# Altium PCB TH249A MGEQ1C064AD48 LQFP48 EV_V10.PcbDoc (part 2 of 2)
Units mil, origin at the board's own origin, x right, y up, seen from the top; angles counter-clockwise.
Board outline 3818.9 x 2637.8 mil, 2 copper layers (Top Layer, Bottom Layer); 103 components, 120 nets, 468 pads, 229 vias.
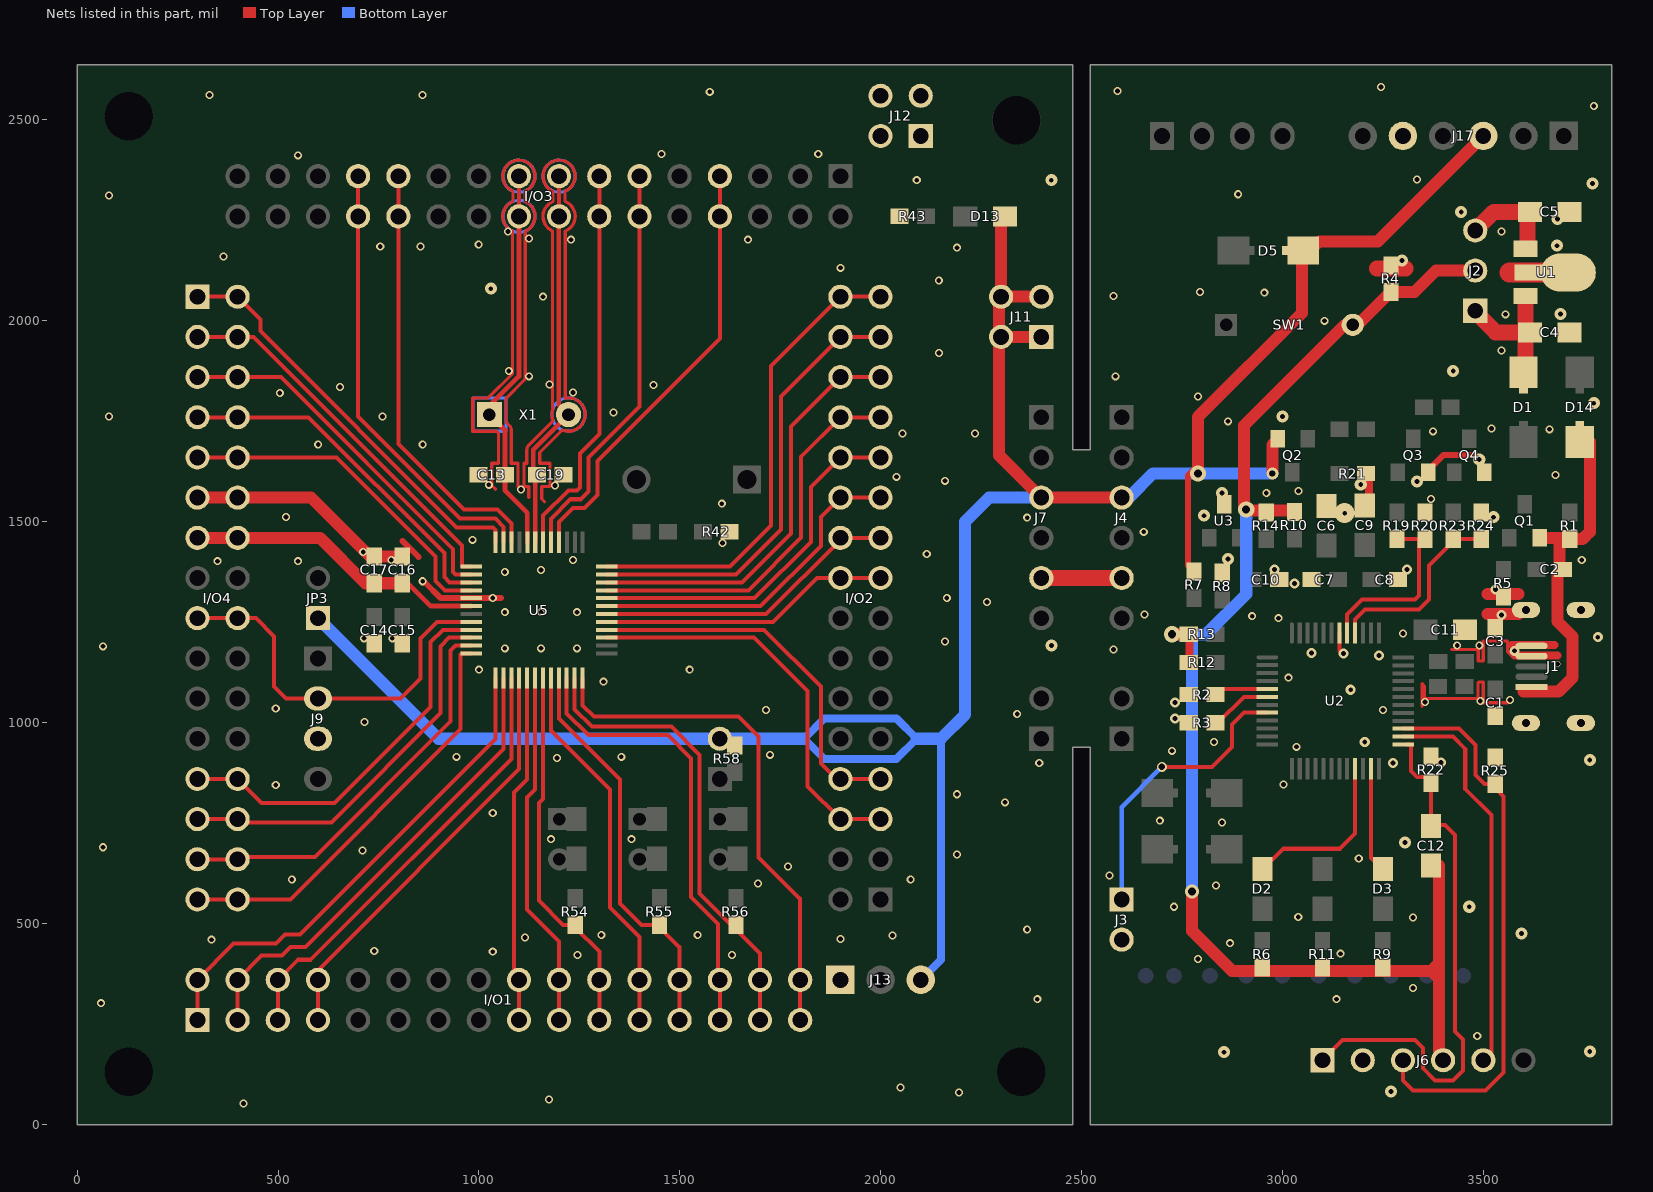
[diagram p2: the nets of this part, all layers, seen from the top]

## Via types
v1: diameter 20, hole 12, Top Layer to Bottom Layer, tented both sides, 163 vias
v2: diameter 30, hole 12, Top Layer to Bottom Layer, tented both sides, 26 vias
v3: diameter 25, hole 12, Top Layer to Bottom Layer, tented both sides, 16 vias
v4: diameter 25, hole 16, Top Layer to Bottom Layer, tented both sides, 13 vias
v5: diameter 40, hole 20, Top Layer to Bottom Layer, tented both sides, 5 vias
v6: diameter 30, hole 16, Top Layer to Bottom Layer, tented both sides, 3 vias
v7: diameter 35, hole 20, Top Layer to Bottom Layer, tented both sides, 1 vias
v8: diameter 50, hole 12, Top Layer to Bottom Layer, tented both sides, 1 vias
v9: diameter 15, hole 12, Top Layer to Bottom Layer, tented both sides, 1 vias

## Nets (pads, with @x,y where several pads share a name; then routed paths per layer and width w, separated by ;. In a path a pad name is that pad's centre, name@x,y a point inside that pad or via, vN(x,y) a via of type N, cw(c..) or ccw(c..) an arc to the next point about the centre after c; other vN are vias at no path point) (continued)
P01: I/O3.23 I/O3.24 U5.34 | length 1076.9
  Top Layer w10: I/O3.23@799.45,2360 I/O3.24@799.45,2260 799.45,1693.03 962.48,1530 1046.61,1530 1081.05,1495.56 U5.34@1081.05,1448.99
P02: I/O3.25 I/O3.26 U5.35 | length 1112.1
  Top Layer w10: I/O3.25@699.45,2360 I/O3.26@699.45,2260 699.45,1761.92 953.37,1508 1040.77,1508 1061.37,1487.41 U5.35@1061.37,1448.99
P03: I/O4.1 I/O4.2 U5.36 | length 1053.7
  Top Layer w10: I/O4.1@299.45,2060 I/O4.2@399.45,2060 ; I/O4.2@399.45,2036.48 I/O4.2@399.45,2060 ; U5.36@1041.68,1448.99 1041.68,1479.25 1034.93,1486 944.25,1486 455.93,1974.32 455.93,2003.52 I/O4.2@399.45,2060
P04: I/O4.3 I/O4.4 U5.37 | length 948.5
  Top Layer w10: I/O4.3@299.45,1960 I/O4.4@399.45,1960 438.59,1960 957.93,1440.66 957.93,1388.52 U5.37@980.71,1388.52
P05: I/O4.5 I/O4.6 U5.38 | length 932
  Top Layer w10: I/O4.5@299.45,1860 I/O4.6@399.45,1860 ; I/O4.6@409.45,1850 I/O4.6@399.45,1860 ; U5.38@980.71,1368.83 942.1,1368.83 935.93,1375 935.93,1431.55 507.48,1860 I/O4.6@399.45,1860
P06: I/O4.7 I/O4.8 U5.39 | length 886.8
  Top Layer w10: I/O4.7@299.45,1760 I/O4.8@399.45,1760 576.37,1760 913.93,1422.44 913.93,1362 926.78,1349.15 U5.39@980.71,1349.15
P07: I/O4.9 I/O4.10 U5.40 | length 853.8
  Top Layer w10: I/O4.9@299.45,1660 I/O4.10@399.45,1660 645.25,1660 891.93,1413.32 891.93,1352.52 914.99,1329.46 U5.40@980.71,1329.46
P10: I/O4.25 I/O4.26 U5.45 | length 979.5
  Top Layer w10: I/O4.25@299.45,860 I/O4.26@399.45,860 459.45,800 640.93,800 879.45,1038.52 879.45,1200.36 910.13,1231.04 U5.45@980.71,1231.04
P11: I/O4.27 I/O4.28 U5.46 | length 982.6
  Top Layer w10: I/O4.27@299.45,760 I/O4.28@399.45,760 ; I/O4.28@389.45,760 I/O4.28@399.45,760 ; U5.46@980.71,1211.35 925.8,1211.35 904.45,1190 904.45,1023.52 632.69,751.76 407.69,751.76 I/O4.28@399.45,760
P12: I/O4.29 I/O4.30 U5.47 | length 1004.7
  Top Layer w10: I/O4.29@299.45,660 I/O4.30@399.45,660 404.94,665.49 591.42,665.49 929.45,1003.52 929.45,1179.64 941.47,1191.67 U5.47@980.71,1191.67
P13: I/O4.31 I/O4.32 U5.48 | length 1043.3
  Top Layer w10: I/O4.31@299.45,560 I/O4.32@399.45,560 530.47,560 954.45,983.98 954.45,1169.29 957.14,1171.98 U5.48@980.71,1171.98
P14: I/O1.1 I/O1.2 U5.1 | length 1241.8
  Top Layer w10: I/O1.1@299.45,260 I/O1.2@299.45,360 389.45,450 494.45,450 517.44,472.99 555,472.99 1041.18,959.18 U5.1@1041.18,1111.01
P15: I/O1.3 I/O1.4 U5.2 | length 1176
  Top Layer w10: I/O1.3@399.45,260 I/O1.4@399.45,360 459.45,420 509.45,420 530.94,441.5 568.04,441.5 1060.87,934.32 U5.2@1060.87,1111.01
P16: I/O1.5 I/O1.6 U5.3 | length 1110.2
  Top Layer w10: I/O1.5@499.45,260 I/O1.6@499.45,360 549.45,410 581.09,410 1080.55,909.46 U5.3@1080.55,1111.01
P17: I/O1.7 I/O1.8 U5.4 | length 1058.4
  Top Layer w10: I/O1.7@599.45,260 I/O1.8@599.45,360 599.45,383.82 1100.24,884.6 U5.4@1100.24,1111.01
P20: I/O1.17 I/O1.18 U5.5 | length 869.3
  Top Layer w10: I/O1.17@1099.45,260 I/O1.18@1099.45,360 1087.63,371.82 1087.63,826.54 1119.92,858.83 U5.5@1119.92,1111.01
P21: I/O1.19 I/O1.20 U5.6 | length 892.5
  Top Layer w10: U5.6@1139.61,1111.01 1139.61,833.52 1119.45,813.36 1119.45,534.9 1199.45,454.9 I/O1.20@1199.45,360 I/O1.19@1199.45,260
P22: I/O1.21 I/O1.22 R54.1 U5.7 | length 924.8
  Top Layer w10: U5.7@1159.29,1111.01 1159.29,809.84 1149.45,800 1149.45,556.9 1209.35,497 R54.1@1239.45,497 1239.45,490 1299.45,430 I/O1.22@1299.45,370 ; I/O1.21@1299.45,260 I/O1.22@1299.45,360
P23: I/O1.23 I/O1.24 U5.8 | length 942.3
  Top Layer w10: U5.8@1178.98,1111.01 1178.98,980.47 1325.93,833.52 1325.93,540 1399.45,466.48 I/O1.24@1399.45,360 I/O1.23@1399.45,260
P24: I/O1.25 I/O1.26 R55.1 U5.9 | length 1002.3
  Top Layer w10: U5.9@1198.66,1111.01 1198.66,1010.79 1350.93,858.52 1350.93,550 1403.93,497 R55.1@1449.45,497 1449.45,490 1499.45,440 ; I/O1.25@1499.45,260 I/O1.26@1499.45,360 ; I/O1.26@1499.45,361.9 1499.45,440 ; 1499.45,441.9 1499.45,440
P25: I/O1.27 I/O1.28 U5.10 | length 1135.8
  Top Layer w10: U5.10@1218.35,1111.01 1218.35,1022.58 1272.14,968.79 1470.66,968.79 1528.24,911.21 1528.24,566.21 1595.19,499.26 1595.19,360 1595.19,355.74 I/O1.28@1599.45,351.48 ; I/O1.27@1599.45,260 I/O1.28@1599.45,351.48 ; I/O1.28@1599.45,360 I/O1.28@1599.45,351.48 ; I/O1.28@1600.93,350 I/O1.28@1599.45,351.48
P26: I/O1.29 I/O1.30 R56.1 U5.11 | length 1165.5
  Top Layer w10: U5.11@1238.03,1111.01 1238.03,1032.9 1280.93,990 1479.45,990 1549.45,920 1549.45,575 1627.45,497 R56.1@1639.45,497 1639.45,485 1699.45,425 I/O1.30@1699.45,360 I/O1.29@1699.45,260
P27: I/O1.31 I/O1.32 U5.12 | length 1286.3
  Top Layer w10: U5.12@1257.72,1111.01 1257.72,1043.22 1285.93,1015 1645.93,1015 1695.93,965 1695.93,665 1799.45,561.48 ; I/O1.31@1799.45,260 I/O1.32@1799.45,360 ; I/O1.32@1799.45,360.42 1799.45,561.48 ; 1799.45,561.9 1799.45,561.48
P32: I/O2.5 I/O2.6 U5.15 | length 1007
  Top Layer w10: U5.15@1318.19,1211.35 1685.04,1211.35 1817.94,1078.45 1817.94,841.51 I/O2.6@1899.45,760 I/O2.5@1999.45,760
P33: I/O2.7 I/O2.8 U5.16 | length 947.1
  Top Layer w10: U5.16@1318.19,1231.04 1709.89,1231.04 1850.93,1090 1850.93,898.52 1889.45,860 I/O2.8@1899.45,860 I/O2.7@1999.45,860
P34: I/O2.17 I/O2.18 U5.17 | length 726.5
  Top Layer w10: U5.17@1318.19,1250.72 1731.65,1250.72 1840.93,1360 I/O2.18@1899.45,1360 I/O2.17@1999.45,1360
P35: I/O2.19 I/O2.20 U5.18 | length 771.6
  Top Layer w10: U5.18@1318.19,1270.41 1714.86,1270.41 1896.95,1452.5 1899.45,1452.5 1906.95,1452.5 I/O2.20@1912.2,1457.76 ; I/O2.20@1899.45,1460 I/O2.19@1999.45,1460
P36: I/O2.21 I/O2.22 U5.19 | length 834.9
  Top Layer w10: U5.19@1318.19,1290.09 1701.02,1290.09 1850.68,1439.75 1850.68,1511.23 I/O2.22@1899.45,1560 I/O2.21@1999.45,1560
P37: I/O2.23 I/O2.24 U5.20 | length 906.3
  Top Layer w10: U5.20@1318.19,1309.78 1685.71,1309.78 1825.93,1450 1825.93,1586.48 I/O2.24@1899.45,1660 I/O2.23@1999.45,1660
P40: I/O2.25 I/O2.26 U5.21 | length 977.6
  Top Layer w10: U5.21@1318.19,1329.46 1670.39,1329.46 1801.18,1460.25 1801.18,1661.73 I/O2.26@1899.45,1760 I/O2.25@1999.45,1760
P41: I/O2.27 I/O2.28 U5.22 | length 1062.6
  Top Layer w10: U5.22@1318.19,1349.15 1655.08,1349.15 1776.43,1470.5 1776.43,1736.98 I/O2.28@1899.45,1860 ; I/O2.28@1885.82,1860 I/O2.28@1899.45,1860 ; I/O2.27@1999.45,1860 I/O2.28@1899.45,1860
P42: I/O2.29 I/O2.30 U5.23 | length 1120.3
  Top Layer w10: U5.23@1318.19,1368.83 1639.76,1368.83 1751.68,1480.75 1751.68,1812.24 I/O2.30@1899.45,1960 I/O2.29@1999.45,1960
P43: I/O2.31 I/O2.32 U5.24 | length 1191.7
  Top Layer w10: U5.24@1318.19,1388.52 1624.45,1388.52 1726.94,1491.01 1726.94,1887.49 I/O2.32@1899.45,2060 I/O2.31@1999.45,2060
P44: J6.5 U2.26 | length 977.3
  Top Layer w10: U2.26@3299.91,965.31 3424.14,965.31 3454.45,935 3454.45,835 3519.45,770 3519.45,180 J6.5@3499.45,160
P45: J6.3 R25.1 U2.27 | length 1381.3
  Top Layer w10: J6.3@3299.45,160 3299.45,110 3324.45,85 3504.45,85 3549.45,130 3549.45,816.22 R25.1@3524.41,841.26 ; U2.27@3299.91,984.99 3439.46,984.99 3479.45,945 3479.45,870 3502.45,847 R25.1@3529.45,847
P46: I/O3.7 I/O3.8 U5.28 | length 1093.5
  Top Layer w10: U5.28@1199.16,1448.99 1199.16,1498.91 1234.25,1534 1262.71,1534 1294.93,1566.23 1294.93,1651.23 1599.45,1955.74 I/O3.8@1599.45,2260 I/O3.7@1599.45,2360
P60: C13.1 I/O3.17 I/O3.18 U5.32 X1.1 | length 980.5
  Top Layer w10: I/O3.18@1099.45,2260 I/O3.17@1099.45,2360
  Top Layer w12: I/O3.18@1099.45,2260 1099.45,1861.64 1026.06,1788.25 X1.1@1026.06,1766.68 1064.49,1728.25 C13.1@1064.49,1616.68 1064.49,1577.9 1120.42,1521.97 U5.32@1120.42,1448.99
P61: C19.1 I/O3.15 I/O3.16 U5.31 X1.2 | length 945.4
  Top Layer w10: I/O3.16@1199.45,2260 I/O3.15@1199.45,2360
  Top Layer w12: C19.1@1135.2,1616.68 1135.2,1678.96 X1.2@1222.56,1766.32 ; U5.31@1140.11,1448.99 C19.1@1140.11,1602.44 ; I/O3.16@1198.74,2261.79 1198.74,2260 1198.74,1790.85 X1.2@1222.91,1766.68 X1.2@1222.56,1766.32 ; X1.2@1222.91,1765.97 X1.2@1222.56,1766.32
P62: I/O3.13 I/O3.14 U5.30 | length 981.4
  Top Layer w10: U5.30@1159.79,1448.99 1159.79,1515.22 1222.58,1578 1243.93,1578 1250.93,1585 1250.93,1669.45 1299.45,1717.97 I/O3.14@1299.45,2260 I/O3.13@1299.45,2360
P63: I/O3.11 I/O3.12 U5.29 | length 1016.9
  Top Layer w10: U5.29@1179.48,1448.99 1179.48,1507.06 1228.41,1556 1253.59,1556 1272.93,1575.34 1272.93,1660.34 1399.45,1786.86 I/O3.12@1399.45,2260 I/O3.11@1399.45,2360
PASS: D3.2 U2.23 | length 264.5
  Top Layer w10: U2.23@3219.75,885.65 3219.75,663.12 3248.43,634.45 D3.2@3249.45,633.43
RST: C12.2 J6.1 R22.2 U2.25 | length 1368.1
  Top Layer w10: J6.1@3099.45,160 3149.45,210 3329.45,210 3349.45,190 3349.45,140 3379.45,110 3424.45,110 3449.45,135 3449.45,211.22 3429.45,231.22 3429.45,719.96 3404.41,745 3384.45,745 3377.84,751.61 C12.2@3369.45,760 ; U2.25@3309.45,945.62 3318.83,945.62 3319.45,945 3319.45,880 3334.45,865 3369.45,865 R22.2@3369.45,850 C12.2@3369.45,760 ; C12.2@3369.45,750 C12.2@3369.45,760
RST_CTRL_51: R19.1 R20.1 U2.41 | length 455
  Top Layer w10: U2.41@3160.7,1223.13 3160.7,1269.12 3197.83,1306.26 3329.41,1306.26 3339.45,1316.3 R20.1@3339.45,1457 ; R19.1@3284.45,1457 R20.1@3339.45,1457 ; R20.1@3354.45,1457 R20.1@3339.45,1457
RST_CTRL_ARM: R23.1 R24.1 U2.40 | length 474.6
  Top Layer w10: U2.40@3180.38,1223.13 3180.38,1256.93 3204.71,1281.26 3339.41,1281.26 3364.45,1306.3 3364.45,1391.3 R23.1@3421.91,1448.76 ; R23.1@3424.45,1457 R24.1@3494.45,1457
TOOL_OPTION0: R2.1 U2.5 | length 135.2
  Top Layer w10: R2.1@2832.45,1070 2846.37,1083.92 U2.5@2961.93,1083.92
TOOL_OPTION1: R3.1 U2.6 | length 156.1
  Top Layer w10: R3.1@2832.45,1000 2839.45,1000 2903.68,1064.23 U2.6@2961.93,1064.23
USBOK: D2.2 U2.21 | length 430.2
  Top Layer w10: D2.2@2949.45,633.42 2950.47,634.45 3002.28,686.26 3142.87,686.26 3180.38,723.77 U2.21@3180.38,885.65
VCAP: C16.1 C17.1 I/O4.13 I/O4.14 U5.42 | length 762.6
  Top Layer w12: C16.1@809.45,1347 C16.1@820.45,1347 ; C16.1@820.09,1337.36 832.73,1337.36 ; C16.1@823.09,1347 832.73,1337.36 ; U5.42@980.71,1290.09 880,1290.09 832.73,1337.36
  Top Layer w20: C16.1@808.45,1336 C16.1@809.45,1336
  Top Layer w30: I/O4.13@299.45,1460 I/O4.14@399.45,1460 604.45,1460 717.45,1347 C17.1@739.45,1347 C16.1@809.45,1347
VCC_USB: C2.1 D14.1 J1.1 Q1.2 R1.1 | length 843.2
  Top Layer w30: 3599.41,1077.48 3619.41,1077.48 3686.89,1077.48 3721.89,1112.48 3721.89,1213.78 3684.41,1251.26 3684.41,1368.26 C2.1@3689.33,1373.18 ; Q1.2@3639.45,1460 3691.45,1460 ; 3689.33,1446.88 3689.33,1381.26 C2.1@3689.33,1373.18 ; C2.1@3697.41,1381.26 C2.1@3689.33,1373.18 ; R1.1@3704.45,1457 R1.1@3714.45,1457 3746.41,1457 3764.41,1475 D14.1@3764.41,1698.39
VCP_OPTION: J3.1 U2.8 | length 722
  Top Layer w10: v4(2699.41,890) 2824.45,890 2874.45,940 2874.45,995 2904.31,1024.86 U2.8@2961.93,1024.86
  Bottom Layer w12: J3.1@2599.45,560 2599.45,790.04 v4(2699.41,890)
VDD: C12.1 J2.2 J6.4 R4.1 R6.1 R9.1 R10.1 R11.1 R12.1 R13.1 R14.2 SW1.2 | length 3588.5
  Top Layer w11: 3357.45,382 3379.45,360 ; 3364.45,390 3382.45,408
  Top Layer w20: v5@2727.52,1215 R13.1@2761.45,1215 ; v5@2732.52,1225 R13.1@2766.45,1225 ; R12.1@2768.45,1150 R13.1@2768.45,1219.56
  Top Layer w30: v7(2774.45,580) 2774.45,481.96 2874.41,382 2949.45,382 3099.45,382 3249.45,382 3357.45,382 3382.45,382 ; R14.2@2964.41,1528 2959.41,1528 2911.41,1528 v5(2909.41,1530) 2904.41,1535 2904.41,1740 3153.16,1988.75 3163.24,1988.75 3168.22,1983.77 3174.45,1977.54 3180.68,1983.77 3268.91,2072 R4.1@3269.45,2072 3328.41,2072 3381.41,2125 J2.2@3479.45,2125 ; R14.2@2969.41,1528 R10.1@3029.41,1528 ; C12.1@3389.45,644.79 3389.45,170 J6.4@3399.45,160 J6.4@3399.45,170
  Bottom Layer w30: v5(2724.45,1220) 2774.45,1220 ; v7(2774.45,580) 2774.45,1220 ; v5(2909.41,1530) 2909.41,1319.96 2809.45,1220 2774.45,1220
VDD3: C5.1 J2.3 U1.1 | length 231.2
  Top Layer w40: J2.3@3479.45,2225 3525.71,2271.26 C5.1@3609.41,2271.26 ; U1.1@3609.41,2195 C5.1@3609.41,2271.26 ; C5.1@3615.2,2271.26 C5.1@3609.41,2271.26
VDD5: C4.1 D1.2 J2.1 U1.3 | length 318.5
  Top Layer w40: J2.1@3477.97,2023.52 3530.24,1971.26 C4.1@3604.41,1971.26 ; D1.2@3604.41,1901.61 C4.1@3604.41,1971.26 ; U1.3@3604.41,2061.26 C4.1@3604.41,1971.26 ; C4.1@3615.2,1971.26 C4.1@3604.41,1971.26
VDUT: D5.2 D13.1 J4.3 J7.3 J11.1 J11.2 J11.3 J11.4 J13.3 J17.3 JP3.1 Q2.2 R7.1 R58.2 | length 6590.5
  Top Layer w15: R7.1@2779.45,1376 2764.45,1391 2764.45,1615.5 2779.45,1630.5 2789.45,1640.5 ; v5@2797.2,1612.75 v5@2799.45,1615
  Top Layer w20: D5.2@3017.56,2175 D5.2@3051.02,2175 D5.2@3068.54,2175
  Top Layer w30: J11.4@2294.45,2060 2294.45,1960 2294.45,1665 J7.3@2399.45,1560 J4.3@2599.45,1560 ; J11.2@2299.45,1960 J11.1@2399.45,1960 ; J11.4@2299.45,2060 D13.1@2299.45,2250.79 ; J11.4@2309.45,2060 J11.3@2399.45,2060 J11.3@2409.45,2060 ; v5(2789.45,1620.5) 2789.45,1640.5 2789.45,1760.91 3048.54,2020 D5.2@3048.54,2170 ; v6@2974.41,1620.5 2974.41,1690.94 Q2.2@2987.41,1703.94 ; D5.2@3063.54,2170 3068.54,2175 3091.3,2197.76 3237.21,2197.76 J17.3@3499.45,2460
  Bottom Layer w20: J13.3@2099.45,360 2149.45,410 2149.45,960 ; 1809.45,960 1859.45,910 2039.45,910 2089.45,960 2039.45,1010 1859.45,1010 1809.45,960
  Bottom Layer w30: JP3.1@599.45,1260 899.45,960 R58.2@1599.45,960 1809.45,960 ; 2089.45,960 2149.45,960 2209.45,1020 2209.45,1500 2269.45,1560 J7.3@2399.45,1560 ; J4.3@2617.48,1560.5 2677.48,1620.5 v5(2789.45,1620.5) v6@2974.41,1620.5
  other v6: 2974.41,1620
VREF+: I/O4.17 I/O4.18 J9.2 U5.44 | length 974.9
  Top Layer w10: I/O4.17@299.45,1260 I/O4.18@399.45,1260 445,1260 490,1215 490,1090 520,1060 J9.2@599.45,1060 804.45,1060 854.45,1110 854.45,1210 895.17,1250.72 U5.44@980.71,1250.72
VSS: C1.2 C3.2 C4.2 C5.2 C6.2 C7.1 C8.1 C9.2 C10.2 C11.2 C13.2 C14.2 C15.2 C16.2 C17.2 C19.2 I/O4.11 I/O4.12 J1.4 J1.5 J1.6 J1.7 J1.8 J1.9 J3.2 J4.5 J6.2 J7.5 J9.3 J12.1 J12.2 J12.3 J12.4 J13.1 J17.5 Q3.3 Q4.3 R2.2 R3.2 R4.2 R5.1 R8.2 R20.2 R21.2 R22.1 R24.2 R25.2 R42.2 R43.1 U1.2 U2.42 U3.3 U5.41 | length 7957.1
  Top Layer w8: 1041.49,1580.68 1034.49,1587.68 1031.99,1587.68 1031.99,1645.68 1048.49,1645.68 1048.49,1721.62 1044.93,1725.18 984.57,1725.18 984.57,1808.17 1023.36,1808.17 1083.45,1868.26 1083.45,2223.34 cw(c1099.45,2260) 1084.45,2297.08 1084.45,2322.92 cw(c1099.45,2360) 1139.45,2360 cw(c1099.45,2360) 1114.45,2322.92 1114.45,2297.08 cw(c1099.45,2260) 1115.45,2223.34 v1@1115.45,1861.64 ; 1075.8,1739.57 cw(c1064.49,1728.25) 1080.49,1728.25 ; v1@1103.99,1580.68 1096.99,1587.68 1096.99,1645.68 1080.49,1645.68 1080.49,1728.25 ; 1123.88,1690.27 ccw(c1135.2,1678.96) 1119.2,1678.96 ; 1124.11,1560 1124.11,1587.68 1111.99,1587.68 1111.99,1645.68 1119.2,1645.68 1119.2,1678.96 ; 1156.11,1587.68 1156.11,1556.64 1163.11,1549.64 ; 1157.13,1587.68 1176.99,1587.68 1176.99,1645.68 1151.2,1645.68 1151.2,1672.33 1207.15,1728.29 ccw(c1222.91,1766.68) 1264.41,1766.68 ccw(c1222.91,1766.68) 1214.74,1807.36 1214.74,2223.04 ccw(c1199.45,2260) 1214.45,2297.08 1214.45,2322.92 ccw(c1199.45,2360) 1239.45,2360 ccw(c1199.45,2360) 1184.45,2322.92 1184.45,2297.08 ccw(c1199.45,2260) 1182.74,2223.66 1182.74,1790.85 ; 3346.95,1040.84 3346.95,1096.97 3352.95,1090.97 3352.95,1060 3418.95,1060 ; 3419.95,1060 3485.95,1060 3485.95,1099.46 ; 3420.79,1182.31 3486.79,1182.31 3486.79,1153.47 3499.45,1153.47 3499.45,1203.5 3559.45,1203.5 3559.45,1177.27 3569.41,1167.31 ; 3487.96,1101.47 3499.45,1101.47 3499.45,1049.5 3559.45,1049.5 v1@3559.45,1056.5 ; 1080.49,1728.25 ccw(c1064.49,1728.25) 1075.79,1739.58 1067.56,1747.81 1067.56,1807.12 1110.75,1850.31 ; 1110.75,1850.31 ccw(c1099.45,1861.64) v1@1115.45,1861.64 ; 1110.76,1850.32 ccw(c1099.45,1861.64) v1@1115.45,1861.64 ; 1119.2,1678.96 cw(c1135.2,1678.96) 1123.9,1690.29 1184.53,1750.92 cw(c1222.91,1766.68) 1184.78,1783.04 ; 1182.74,1790.85 ccw(c1198.74,1790.85) 1184.78,1783.04 ; 1182.74,1790.85 ccw(c1198.74,1790.85) 1184.78,1783.04
  Top Layer w10: I/O4.11@299.45,1560 I/O4.12@399.45,1560 ; 3141.01,1179.01 U2.42@3141.01,1223.13
  Top Layer w15: 809.5,1452.55 849.77,1412.28 ; v1@864.4,1350.05 904.67,1309.78 1054.45,1309.78 ; Q3.3@3369.7,1635.29 3400.65,1666.24 3478.11,1666.24 v2(3489.35,1655)
  Top Layer w20: C9.2@3214.45,1528 R21.2@3214.45,1625.53 ; 3570.48,1192.9 3676.39,1192.9 ; v3@3576.62,1167.31 3684.35,1167.31
  Top Layer w30: I/O4.11@299.45,1560 I/O4.12@399.45,1560 582.45,1560 C17.2@729.45,1413 ; C17.2@739.45,1413 C16.2@809.45,1413 ; 3509.45,1270 J1.6@3586.45,1270 ; 3509.45,1320 3586.45,1320
  Top Layer w40: J7.5@2399.45,1360 J4.5@2599.45,1360 ; 3234.35,2130 3305.45,2130
  Top Layer w50: 3564.41,2120.31 U1.2@3628.03,2120.31 U1.2@3704.41,2120.31
  Bottom Layer w8: 984.57,1725.18 1067.56,1725.18 1067.56,1808.17 984.57,1808.17 984.57,1725.18 ; 1139.45,2260 ccw(c1099.45,2260) 1139.45,2260 ; 1139.45,2360 ccw(c1099.45,2360) 1139.45,2360 ; 1239.45,2360 ccw(c1199.45,2360) 1239.45,2360 ; 1264.41,1766.68 ccw(c1222.91,1766.68) 1264.41,1766.68
  other v1: 414.45,51.9 1174.45,61.9 2194.35,80 2049.45,91.9 3484.35,220 59.45,301.9 2389.45,311.9 3134.41,311.9 3324.35,340 2789.41,411.9 1245,421.9 1629.45,421.9 3144.35,425 1034.35,430 739.45,431.9 2869.41,451.26 334.35,460 1899.45,461.9 1114.35,465 2029.45,470 1304.45,471.9 1544.45,471.9 2364.35,485 3324.35,515 3038.9,516.26 2729.41,541.9 2834.35,595 1694.35,600 534.35,610 2074.35,610 2569.45,620 1769.45,641.9 3189.45,661.9 2189.45,671.9 710,681.9 64.35,690 1179.45,710 1379.45,710 2849.45,751.9 2694.35,756 1034.35,775 2309.45,801.9 2189.45,821.9 494.35,845 3002.45,846 2394.35,900 1194.45,911.9 944.35,915 1354.35,915 1724.35,920 2724.35,930 3034.35,940 2829.41,951.9 715,1001.9 2339.45,1021.9 1714.45,1031.9 3249.45,1031.9 494.35,1035 3354.41,1051.26 3491.95,1054 3565.45,1056.5 1310,1101.9 3014.45,1111.9 1000,1131.9 1524.45,1131.9 2579.45,1181.9 1064.35,1185 1154.35,1185 1244.35,1185 64.35,1190 3434.41,1191.84 3489.41,1191.9 2159.45,1201.9 714.35,1210 784.35,1210 3299.45,1221.9 2989.45,1260 2924.35,1265 2656.41,1269.26 1064.35,1275 1154.35,1275 1244.35,1275 2264.35,1300 1034.35,1310 2164.35,1310 860,1351.9 1064.35,1375 1154.35,1380 349.45,1401.9 550,1401.9 781.89,1405 1234.35,1405 3744.35,1405 2114.35,1420 711.89,1425 1605.93,1447.44 984.35,1455 2654.35,1475 2364.35,1510 520,1511.9 1604.35,1545 3369.41,1556.93 2959.41,1571.9 3039.41,1576.26 1104.45,1580 1189.45,1590 1024.45,1591.9 2159.45,1601.9 2039.45,1611.9 3679.41,1616.26 600,1691.9 860,1691.9 2054.35,1720 2234.35,1720 3374.35,1725 3664.35,1730 3519.41,1731.9 2864.35,1750 79.45,1761.9 760,1761.9 1335,1771.9 2789.45,1811.9 504.35,1820 1234.45,1821.9 654.35,1835 1434.35,1840 1175.74,1841.9 1124.45,1861.9 2584.41,1861.9 1074.35,1875 2145,1920 3544.41,1926.26 3104.35,2000 3554.35,2016.26 1159.45,2060 2579.41,2061.9 2954.35,2070 2794.45,2071.9 2144.35,2100 1899.45,2131.9 364.35,2160 2189.45,2181.9 754.35,2185 854.35,2185 999.45,2190 1229.45,2201.9 1669.45,2201.9 1124.35,2205 1071.92,2221.9 3544.41,2221.9 79.45,2311.9 2889.45,2315 2089.45,2350 3334.45,2351.9 549.45,2411.9 1454.35,2415 1844.35,2415 3774.35,2535 329.45,2561.9 859.45,2561.9 1574.35,2570 2589.41,2571.9 3244.41,2581.9
  other v2: 3269.45,81.9 2854.35,180 3764.45,181.9 3594.35,475 3464.41,541.9 3304.45,701.9 3764.45,906.9 2424.45,1191.9 2864.41,1406.93 3524.41,1511.26 2804.35,1515 2849.45,1571.9 3194.41,1592.44 3334.35,1600 2999.41,1761.9 3774.35,1795 3424.41,1875 3691.45,2016.9 1029.45,2080 3297.01,2150 3682.45,2186.9 3684.35,2253 3444.35,2271 3771.45,2341.9 2424.35,2350
  other v3: 3274.35,900 3394.41,901.26 3204.41,951.9 2732.52,1010 2732.52,1050 3169.45,1081.9 3239.45,1167 3151.45,1172 3071.45,1173 3576.62,1178.86 3784.35,1212.71 3544.35,1268 3529.41,1331.26 3029.41,1346.26 2979.41,1381.26 3309.41,1381.26
  other v8: 3154.41,1521.26
  other v9: 3684.35,1146.26
pads on no net: J6.6 J7.1 J9.4 U2.1 U2.2 U2.3 U2.4 U2.7 U2.24 U2.28 U2.29 U2.30 U2.32 U2.37 U2.38 U2.39 U2.46
copper on no net: | length 251.3
  Bottom Layer w8: 1239.45,2260 ccw(c1199.45,2260) 1239.45,2260

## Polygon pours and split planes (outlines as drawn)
VSS on Bottom Layer "Top Layer-No Net" (hatched 90Degree grid 10 track 10, remove dead copper, pour order 1001): 29.45,30 3789.45,30 3789.45,2610 29.45,2610
VSS on Top Layer "Top Layer-No Net" (hatched 90Degree grid 10 track 10, remove dead copper, pour order 1001): 29.45,30 3789.45,30 3789.45,2610 29.45,2610

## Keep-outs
Keep-Out Layer:
  circle w7.88: c128.35,131.26 r122.58
  circle w7.88: c2349.45,131.26 r122.58
  circle w7.88: c2337.8,2499.06 r122.58
  circle w7.88: c128.35,2509.06 r122.58
  lines w15: 3818.9,1.26 3818.9,2639.06

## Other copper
Top Layer:
  pour cut-out: 2439.45,2639.06 2559.45,2639.06 2559.45,0 2439.45,0
Bottom Layer:
  pour cut-out: 2439.45,2639.06 2559.45,2639.06 2559.45,0 2439.45,0

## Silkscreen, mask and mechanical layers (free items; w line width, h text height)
Top Overlay:
  circle w5: c128.35,2509.06 r120
  circle w5: c128.35,131.26 r120
  circle w5: c2349.45,131.26 r120
  circle w5: c2337.8,2499.06 r120
  region: 1999.45,450 2009.45,450 2009.45,420 2019.45,420 2004.45,405 1989.45,420 1999.45,420
  text "GND" at 1789.45,2560 h50
  text "P02" at 724.45,2425 h40 r90
  text "P01" at 824.45,2425 h40 r90
  text "P00" at 924.45,2425 h40 r90
  text "P60" at 1124.45,2425 h40 r90
  text "P61" at 1224.45,2425 h40 r90
  text "P62" at 1324.45,2425 h40 r90
  text "P63" at 1424.45,2425 h40 r90
  text "P46" at 1624.45,2425 h40 r90
  text "P45" at 1724.45,2425 h40 r90
  text "P44" at 1824.45,2425 h40 r90
  text "RST" at 1924.45,2425 h40 r90
  text "When J16 Open," at 2564.45,2335 h45
  text "Power" at 2149.45,2320 h50
  text "SCL" at 3619.45,2320 h35 r90
  text "CLK" at 3719.45,2320 h35 r90
  text "RST" at 3219.45,2310 h37 r90
  text "GND" at 3319.45,2305 h37 r90
  text "SDA" at 3419.45,2305 h37 r90
  text "VCC" at 3519.45,2305 h37 r90
  text "SW1 must be off." at 2564.45,2260 h45
  text "VDD3" at 3289.41,2201.9 h37
  text "VDUT" at 2249.45,2130 h50
  text "VDD" at 3319.45,2105 h37
  text "P03" at 129.45,2040 h40
  text "P43" at 2059.45,2040 h40
  text "VDD5" at 3289.41,1991.9 h37
  text "2023.07" at 1439.45,1990 h40
  text "TH249A" at 479.45,1980 h60
  text "P04" at 129.45,1940 h40
  text "P42" at 2059.45,1940 h40
  text "MGEQ1C064AD48 LQFP48 EV_V10" at 489.45,1890 h50
  text "Power On" at 3099.45,1845 h45
  text "P05" at 129.45,1840 h40
  text "P41" at 2059.45,1840 h40
  text "Power Off" at 2669.45,1840 h45
  text "P06" at 129.45,1740 h40
  text "P40" at 2059.45,1740 h40
  text "RESET" at 1419.45,1720 h50
  text "P07" at 129.45,1640 h40
  text "P37" at 2059.45,1640 h40
  text "SCL" at 2239.45,1640 h35
  text "GND" at 129.45,1540 h40
  text "P36" at 2059.45,1540 h40
  text "VDUT" at 2209.45,1540 h35
  text "Vcap" at 104.45,1440 h40
  text "P35" at 2059.45,1440 h40
  text "SDA" at 2239.45,1440 h35
  text "U5 current" at 585.93,1435 h45 r90
  text "measurement" at 645.93,1430 h40 r90
  text "VDD" at 129.45,1340 h40
  text "P34" at 2059.45,1340 h40
  text "GND" at 2239.45,1340 h35
  text "VREF+" at 64.45,1240 h40
  text "RST" at 2239.45,1240 h35
  text "Chip VDD" at 664.35,1105 h40
  text "↓" at 2329.45,1090 h110 r90
  text "↓" at 2719.45,1060 h100 r90
  text "P31_TX" at 2139.45,1040 h37
  text "VREF+" at 665,1031.9 h40
  text "↓" at 2669.45,960 h100 r270
  text "P30_RX" at 2139.45,950 h37
  text "GND" at 665,941.9 h40
  text "↓" at 2279.45,930 h110 r270
  text "P10" at 129.45,840 h40
  text "P33" at 2059.45,840 h40
  text "P11" at 129.45,740 h40
  text "P32" at 2059.45,740 h40
  text "P12" at 129.45,640 h40
  text "P31" at 2059.45,640 h40
  text "P13" at 129.45,540 h40
  text "P30" at 2059.45,540 h40
  text "P31_TX" at 1929.45,460 h37
  text "GND" at 1859.45,410 h35
  text "VDD" at 2099.45,410 h35
  text "ISP" at 2169.45,310 h50
  text "J3 Open : Disable VCP." at 2552.45,300 h45
  text "J3 Short : Enable VCP." at 2547.45,225 h45
  text "P14" at 324.45,100 h40 r90
  text "P15" at 424.45,100 h40 r90
  text "P16" at 524.45,100 h40 r90
  text "P17" at 624.45,100 h40 r90
  text "P20" at 1119.45,100 h40 r90
  text "P21" at 1219.45,100 h40 r90
  text "P22" at 1324.45,100 h40 r90
  text "P23" at 1424.45,100 h40 r90
  text "P24" at 1524.45,100 h40 r90
  text "P25" at 1619.45,100 h40 r90
  text "P26" at 1724.45,100 h40 r90
  text "P27" at 1824.45,100 h40 r90
Mechanical 1:
  circle w7.88: c2499.45,1010 r33
  circle w7.88: c2499.45,1300 r25
  circle w7.88: c2499.45,1418 r25
  circle w7.88: c2499.45,1505 r27
  circle w7.88: c2499.45,1615 r27
  lines w7.88: 2477.8,1080 2521.1,1080 2521.1,1234 2477.8,1234 2477.8,1080
  lines w8.88: 0,0 0,2637.8 2477.8,2637.8 2477.8,1678.74 2521.1,1678.74 2521.1,2637.8 3818.9,2637.8 3818.9,0 2521.1,0 2521.1,938.74 2477.8,938.74 2477.8,0 0,0
Mechanical 2:
  lines w6: 2499.45,1033 2499.45,1010 2522.45,1010 ; 2499.45,1323 2499.45,1300 2522.45,1300 ; 2499.45,1443 2499.45,1420 2522.45,1420 ; 2499.45,1528 2499.45,1505 2522.45,1505 ; 2499.45,1638 2499.45,1615 2522.45,1615
Drill Drawing:
  text ".Legend" at 3899.41,16.26 h40

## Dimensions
0,0 to 0,2637.8 on Top Overlay
0,0 to 3818.9,0 on Top Overlay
